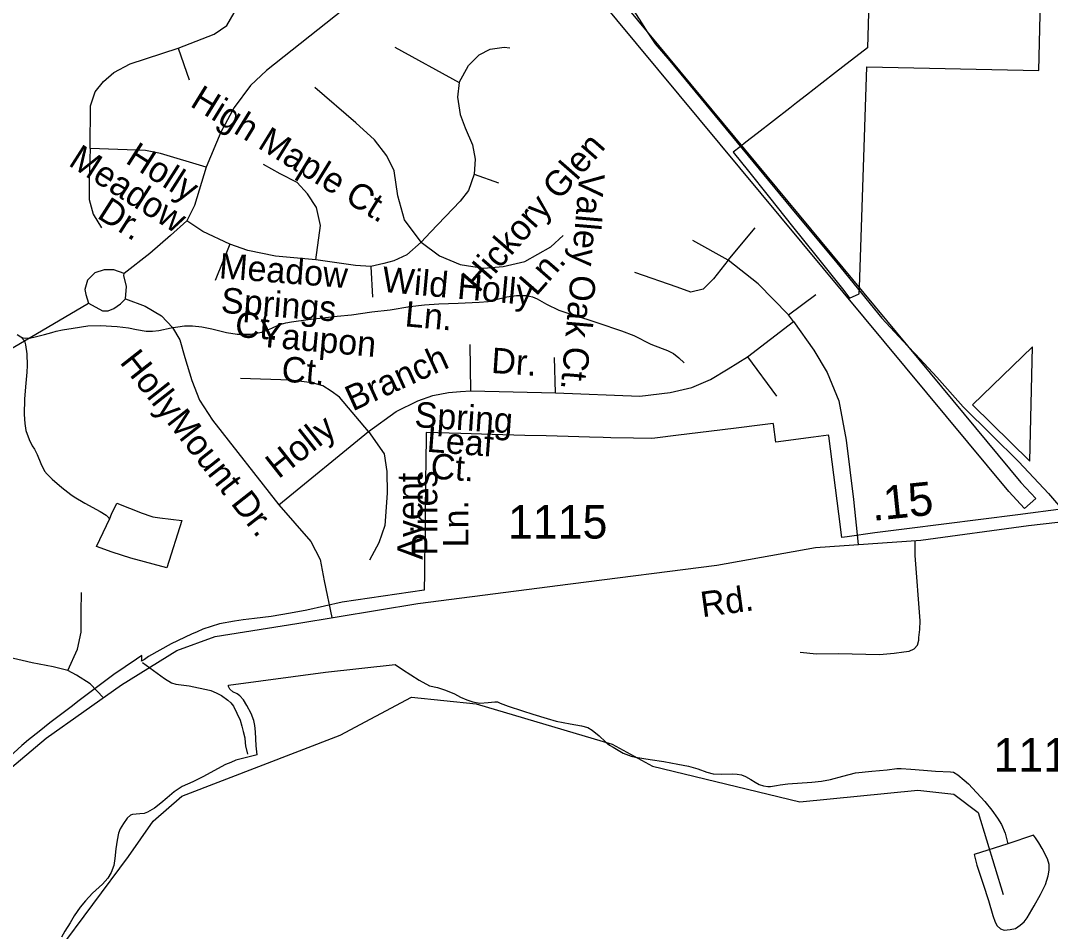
# Model space of a CAD drawing. Extents: x 2001466 to 2224147, y 644118 to 847247.
# Drawn here: x 2039763 to 2043610, y 683440 to 686843 of the extents above; entities that cross this region are included whole.
import ezdxf

# ---------------------------------------------------------------- set-up
doc = ezdxf.new("R2010")
doc.units = 0
for name, color, linetype in [('Exist Aviation Commercial or Municipal Perimeter Paved', 7, 'Continuous'), ('Exist Boundary Political City Limit New', 7, 'Continuous'), ('Exist Boundary Political City Limit New Hole', 7, 'Continuous'), ('Exist Hydrographic Creek Single Shore', 7, 'Continuous'), ('Exist Hydrographic Misc Water Feature', 7, 'Continuous'), ('Exist Road Non-System Type 51', 7, 'Continuous'), ('Exist Road Non-System Type 51 Label', 7, 'Continuous'), ('Exist Road Secondary Mileage Hundredths English Label', 7, 'Continuous'), ('Exist Road Secondary Type 51 Attributed', 7, 'Continuous'), ('Exist Road Secondary Type 51 Label', 7, 'Continuous'), ('Exist Road Secondary Type 51 Number Label', 7, 'Continuous'), ('Map Preparation Boundary City Limit Buffer Line', 7, 'Continuous')]:
    doc.layers.add(name, color=color, linetype=linetype)

msp = doc.modelspace()

# ---------------------------------------------------------------- linework, layer by layer
at = {"layer": 'Exist Aviation Commercial or Municipal Perimeter Paved'}
msp.add_line((2042103.6, 686800.8), (2043075.5, 685628.1), dxfattribs=at)
msp.add_lwpolyline([(2043075.5, 685628.1), (2043498.8, 685117.4), (2043555, 685057.6), (2043513, 685019.5), (2043454.9, 685083.5), (2041370.9, 687591.4), (2041340.9, 687627.4), (2041386.6, 687665.5), (2041415.7, 687630.7), (2042103.6, 686800.8)], dxfattribs=at)
at = {"layer": 'Exist Boundary Political City Limit New'}
for points in [[(2042930.2, 686871.1), (2042926.1, 686741.4), (2042834.8, 686670.2), (2042806.5, 686648.1), (2042756, 686608.8), (2042699, 686564.4), (2042661.1, 686535.4), (2042636.1, 686515.7), (2042575.5, 686468), (2042514.4, 686420.4), (2042471.8, 686388.4), (2042450.8, 686370.8), (2042425.1, 686350.8), (2042430, 686344.8), (2042477.1, 686286.3), (2042560.4, 686181.8), (2042646.8, 686073.6), (2042688.1, 686021.7), (2042738.1, 685959), (2042837.9, 685833.9), (2042858.9, 685805.8), (2042896, 685822.4), (2042897.2, 685846.9), (2042909.2, 686219.6), (2042923.8, 686669.9), (2043566.8, 686655.9), (2043576.2, 687073.3)], [(2043658.9, 685019.1), (2043488.1, 684995.6), (2043073, 684943.5), (2042953.8, 684929.1), (2042851, 684914), (2042831.2, 684911.6), (2042819.6, 685000), (2042781.8, 685290.9), (2042781.5, 685293.2), (2042724.6, 685285.8), (2042584, 685267.6), (2042575, 685334.9), (2042574.6, 685337.9), (2042525, 685331.6), (2042435.9, 685320.3), (2042334.5, 685307.5), (2042220.9, 685293.6), (2042132.2, 685282.6), (2042119.5, 685281.2), (2042051.9, 685283.1), (2041968.4, 685284.3), (2041939.2, 685284.8), (2041887.8, 685286.2), (2041807.9, 685288.5), (2041725.9, 685290.8), (2041646, 685293.1), (2041564.5, 685295.2), (2041484.6, 685297.6), (2041407.5, 685299.9), (2041277.6, 685303.4), (2041277.5, 685299.9), (2041276.2, 685184.2), (2041275.6, 685139.5), (2041275.4, 685103.9), (2041274.5, 685022.6), (2041274.4, 685000), (2041274.2, 684927.7), (2041272.1, 684828.3), (2041271.4, 684777.7), (2041271, 684714.9), (2040964.2, 684669.4), (2040832.1, 684640.4), (2040770.9, 684628.4), (2040699.2, 684616.1), (2040636.6, 684608.4), (2040594, 684603.8), (2040561.5, 684599.2), (2040505.6, 684588.4), (2040444, 684568.5), (2040422.9, 684559.6), (2040401.1, 684550.4), (2040325, 684514.6), (2040241.5, 684466.3), (2040225.5, 684455.8), (2040215.2, 684449.1), (2040215.5, 684452.9)], [(2040215.5, 684452.9), (2040216.4, 684470.1), (2040196.1, 684457.2), (2040153.8, 684428.8), (2040111.9, 684399.7), (2040085.9, 684380.9), (2039982.4, 684302.1), (2039952.1, 684279.2), (2039912.2, 684249), (2039872.5, 684218.6), (2039832.4, 684187.2), (2039792.6, 684155.2), (2039767.6, 684133.8), (2039692.2, 684065)]]:
    msp.add_lwpolyline(points, dxfattribs=at)
at = {"layer": 'Exist Boundary Political City Limit New Hole'}
msp.add_lwpolyline([(2043542.8, 685623.9), (2043318.8, 685407.2), (2043532.6, 685196.8), (2043542.8, 685623.9)], dxfattribs=at)
at = {"layer": 'Exist Hydrographic Creek Single Shore'}
msp.add_lwpolyline([(2039064.6, 682482.2), (2039450.9, 683035.3), (2039650, 683211.6), (2039900, 683360.8), (2040165.9, 683719.5), (2040258, 683852.2), (2040365.8, 683945.1), (2040957, 684172.6), (2041223, 684314.8), (2041464.9, 684290.2), (2041972.8, 684138.8), (2042122.9, 684057), (2042673.9, 683924.4), (2043115, 683967.9), (2043248.9, 683952.1), (2043339.9, 683884.6), (2043432.8, 683577.6)], dxfattribs=at)
at = {"layer": 'Exist Hydrographic Misc Water Feature'}
for points in [[(2039763.8, 685661.6), (2039771.8, 685657.6), (2039781.8, 685655.6), (2039801.9, 685657.6), (2039817.9, 685661.6), (2039851.8, 685669.7), (2039879.7, 685677.8), (2039895.6, 685681.8), (2039919.6, 685687.8), (2039959.8, 685694), (2040013.8, 685702), (2040061.7, 685704.1), (2040123.7, 685700.2), (2040165.7, 685694.3), (2040195.6, 685688.4), (2040231.7, 685682.4), (2040255.7, 685682.5), (2040279.7, 685684.5), (2040325.6, 685694.6), (2040375.7, 685702.7), (2040405.6, 685702.8), (2040439.7, 685698.8), (2040477.6, 685690.9), (2040531.7, 685677), (2040571.7, 685671.1), (2040595.7, 685671.1), (2040621.7, 685671.2), (2040663.6, 685679.2), (2040701.5, 685693.3), (2040727.5, 685705.4), (2040753.6, 685713.4), (2040775.5, 685717.4), (2040837.5, 685725.6), (2040945.5, 685737.8), (2040999.4, 685743.9), (2041075.5, 685754), (2041143.4, 685762.1), (2041217.4, 685774.3), (2041271.3, 685780.4), (2041325.3, 685784.5), (2041397.5, 685786.6), (2041475.4, 685790.8), (2041509.4, 685792.8), (2041533.2, 685798.9), (2041579.1, 685811), (2041615.2, 685815), (2041653.2, 685815.1), (2041675.3, 685811.1), (2041693.1, 685803.2), (2041727.2, 685783.3), (2041773.3, 685761.4), (2041829.3, 685741.5), (2041881.4, 685725.6), (2041919.3, 685713.6), (2042007.5, 685683.8), (2042053.4, 685665.9), (2042117.4, 685634), (2042159.4, 685618.1), (2042179.5, 685610.2), (2042201.7, 685598.3), (2042221.6, 685582.3), (2042241.7, 685564.3)], [(2039749.9, 685669.5), (2039763.8, 685661.6)], [(2039763.8, 685661.6), (2039777.9, 685645.6), (2039781.8, 685631.6), (2039785.9, 685597.6), (2039788, 685553.6), (2039786.2, 685529.6), (2039782.1, 685487.6), (2039778.2, 685429.6), (2039776.3, 685371.6), (2039778.6, 685337.6), (2039782.5, 685311.6), (2039794.6, 685277.7), (2039806.7, 685253.7), (2039814.7, 685241.7), (2039824.5, 685221.8), (2039838.6, 685187.7), (2039852.8, 685159.8), (2039862.6, 685147.8), (2039880.9, 685129.9), (2039916.8, 685097.9), (2039950.8, 685072), (2039962.9, 685064), (2040002.9, 685040.2), (2040060.9, 685008.2), (2040082.9, 684994.3), (2040091.1, 684986.3), (2040097, 684982.3)], [(2040097, 684982.3), (2040103, 684998.3), (2040123.1, 685040.3), (2040217, 685002.5), (2040249, 684990.6), (2040257, 684988.6), (2040283, 684984.6), (2040365, 684974.8), (2040309.2, 684798.7), (2040175.3, 684834.4), (2040105.4, 684856.3), (2040047.2, 684878.2), (2040097, 684982.3)], [(2040646.6, 684099.5), (2040642.7, 684133.5), (2040640.4, 684185.4), (2040638.3, 684209.4), (2040634.2, 684227.5), (2040624.4, 684253.4), (2040608.4, 684283.4), (2040596.1, 684305.3), (2040582.2, 684319.3), (2040572.1, 684327.3), (2040556.1, 684335.3), (2040544.2, 684345.3), (2040540.1, 684355.3), (2040540.1, 684359.3), (2040901.8, 684407.9), (2041161.8, 684436.4), (2041189.9, 684418.5), (2041251.9, 684378.6), (2041290, 684356.7)], [(2041290, 684356.7), (2041320.1, 684350.7), (2041350.1, 684340.8), (2041384.1, 684326.8), (2041406.1, 684314.9), (2041430.1, 684305), (2041452, 684297), (2041478, 684293), (2041510, 684295.1), (2041534, 684297.1), (2041544.1, 684297.1), (2041554.1, 684293.1), (2041584, 684281.2), (2041638.2, 684263.4), (2041676.1, 684251.4), (2041730.3, 684235.5), (2041764.1, 684225.6), (2041816.2, 684215.7), (2041858.2, 684207.8), (2041882.2, 684201.8), (2041898.2, 684191.9), (2041924.2, 684169.9), (2041948.2, 684148), (2041962.4, 684136), (2041976.3, 684128), (2042014.2, 684106.1), (2042044.4, 684094.2), (2042060.4, 684090.2), (2042114.5, 684082.3), (2042166.4, 684074.4), (2042218.5, 684064.5), (2042258.5, 684056.6), (2042292.5, 684046.6), (2042326.3, 684034.7), (2042350.3, 684028.7), (2042380.5, 684026.8), (2042420.5, 684028.9), (2042440.3, 684026.9), (2042456.3, 684025), (2042470.5, 684019), (2042490.4, 684007), (2042506.4, 683997.1), (2042522.4, 683989.1), (2042538.6, 683983.1), (2042554.6, 683981.2), (2042564.6, 683981.2), (2042586.3, 683985.3), (2042600.5, 683987.3), (2042628.4, 683991.3), (2042718.4, 683997.5), (2042754.5, 684001.6), (2042788.3, 684007.6), (2042834.5, 684019.7), (2042882.2, 684031.8), (2042942.3, 684037.9), (2043000.3, 684044), (2043036.2, 684048.1), (2043052.2, 684048.1), (2043088.3, 684046.2), (2043136.3, 684042.3), (2043180.4, 684038.3), (2043236.4, 684036.5), (2043248.3, 684034.5), (2043264.2, 684024.5), (2043288.2, 684004.6), (2043304.2, 683990.6), (2043364.3, 683924.7), (2043390.6, 683892.8), (2043412.5, 683862.8), (2043426.6, 683838.8), (2043440.6, 683806.9), (2043450.8, 683766.9)], [(2040646.6, 684099.5), (2040606.8, 684089.4), (2040566.6, 684079.3), (2040548.7, 684071.3), (2040528.6, 684063.3), (2040484.8, 684039.2), (2040446.8, 684019.1), (2040406.8, 683999.1), (2040366.9, 683981), (2040336.9, 683961), (2040310.9, 683938.9), (2040287.1, 683918.8), (2040263.1, 683900.8), (2040237.1, 683884.8), (2040225, 683880.7), (2040209, 683878.7), (2040181.1, 683876.6), (2040173.1, 683874.6), (2040161.2, 683862.6), (2040147.2, 683842.6), (2040135.2, 683822.6), (2040129.2, 683806.6), (2040123.3, 683780.6), (2040119.4, 683748.5), (2040115.5, 683712.5), (2040111.4, 683686.5), (2040101.5, 683660.5), (2040089.6, 683638.5), (2040069.5, 683616.4), (2040031.6, 683582.4), (2040005.8, 683554.4), (2039985.9, 683530.3), (2039963.7, 683498.3), (2039947.9, 683472.3), (2039927.8, 683440.2), (2039915.9, 683418.2)], [(2043450.8, 683766.9), (2043324.7, 683726.7), (2043335, 683686.7), (2043359, 683616.8), (2043379.1, 683554.8), (2043395.3, 683498.8), (2043403.3, 683474.9), (2043411.3, 683460.9), (2043423.4, 683448.9), (2043437.3, 683445), (2043459.2, 683447), (2043479.3, 683451), (2043497.2, 683463.1), (2043511.3, 683475.1), (2043523.2, 683491.1), (2043549.1, 683535.1), (2043573.1, 683577.2), (2043591.1, 683615.2), (2043600.9, 683647.2), (2043604.8, 683669.2), (2043604.8, 683689.2), (2043598.7, 683711.2), (2043578.8, 683749.1), (2043566.7, 683771.1), (2043554.6, 683789.1), (2043546.6, 683799.1), (2043450.8, 683766.9)]]:
    msp.add_lwpolyline(points, dxfattribs=at)
at = {"layer": 'Exist Road Non-System Type 51'}
msp.add_line((2043104.9, 684843.7), (2043104, 684899.7), dxfattribs=at)
for points in [[(2040352, 686739.3), (2040485.7, 686791.6), (2040534.1, 686824.6), (2040561.3, 686871.1), (2040576.8, 686937), (2040573.8, 687066)], [(2040968.8, 686884.5), (2040681.4, 686655.9), (2040621.3, 686599.7), (2040561.3, 686518.2), (2040510.9, 686425.2), (2040456.6, 686295.3)], [(2042053.8, 686879.3), (2042090.6, 686820.5), (2042103.6, 686800.8)], [(2042103.6, 686800.8), (2042133.3, 686755.6), (2042188, 686692.5), (2042340.2, 686507.4), (2042638.8, 686145.3), (2042812.6, 685937.8), (2042980.4, 685730.4), (2043075.5, 685628.1)], [(2041160.7, 686743.1), (2041400.9, 686611.3)], [(2041400.9, 686611.3), (2041435.8, 686675.3), (2041476.5, 686714.1), (2041517.2, 686735.4), (2041569.5, 686743.1), (2041590.8, 686741.2)], [(2040022.6, 686365.1), (2040024.6, 686524.1), (2040042, 686576.4), (2040073, 686615.2), (2040111.8, 686648.1), (2040171.8, 686681.1), (2040352, 686739.3)], [(2040352, 686739.3), (2040392.7, 686621)], [(2041259.5, 686015.3), (2041197.5, 686098.7), (2041172.3, 686187.9), (2041158.8, 686280.9), (2041131.6, 686337.2), (2041085.1, 686397.3), (2041015.4, 686461.2), (2040862.3, 686593.1)], [(2041400.9, 686611.3), (2041395.1, 686556.2), (2041404.8, 686492.3), (2041424.2, 686441.9), (2041451.3, 686377.9), (2041461, 686325.5), (2041457.1, 686269.3)], [(2040022.6, 686365.1), (2040019.2, 686245.8), (2040019.2, 686174.8), (2040034.4, 686119), (2040064.8, 686068.3)], [(2040456.6, 686295.3), (2040286.1, 686345.7), (2040229.9, 686357.3), (2040022.6, 686365.1)], [(2040456.6, 686295.3), (2040412.1, 686152.2), (2040383.8, 686094.1)], [(2040866.2, 685948.6), (2040883.6, 686076.6), (2040868.1, 686144.5), (2040835.2, 686194.9), (2040796.5, 686237.5), (2040732.5, 686270.5), (2040670.5, 686305.4)], [(2041457.1, 686269.3), (2041435.8, 686207.3), (2041404.8, 686168.5), (2041294.4, 686052.2), (2041259.5, 686015.3)], [(2041457.1, 686269.3), (2041548.2, 686236.4)], [(2040383.8, 686094.1), (2040322.9, 686039.8), (2040245.4, 685971.9), (2040150.5, 685898.2), (2040111.8, 685911.8), (2040074.9, 685911.8), (2040040.1, 685900.2), (2040013, 685873), (2040003.3, 685838.1), (2040006.5, 685819.7), (2040016.7, 685786.8), (2040069.1, 685758.6), (2040090.4, 685758.6), (2040111.8, 685766.4), (2040136.9, 685783.9), (2040154.4, 685803.2), (2040158.3, 685849.8), (2040148.6, 685890.5), (2040150.5, 685898.2)], [(2040544.6, 686006.8), (2040443.8, 686055.3), (2040383.8, 686094.1)], [(2042405.7, 685947.9), (2042506.5, 686068.1)], [(2041259.5, 686015.3), (2041205.3, 685968), (2041156.8, 685944.8), (2041120, 685935.1), (2041071.6, 685923.4)], [(2041259.5, 686015.3), (2041327.3, 685964.2), (2041404.8, 685931.2), (2041492, 685917.6), (2041565.6, 685923.4), (2041647, 685942.8), (2041743.9, 685997.1), (2041790.4, 686039.8)], [(2042405.7, 685947.9), (2042274, 686021.5)], [(2040544.6, 686006.8), (2040490.3, 685871.1)], [(2040866.2, 685948.6), (2040715.1, 685962.2), (2040612.4, 685983.5), (2040544.6, 686006.8)], [(2041071.6, 685923.4), (2041013.5, 685927.3), (2040866.2, 685948.6)], [(2042405.7, 685947.9), (2042351.5, 685878.1), (2042312.7, 685839.3), (2042266.2, 685827.7), (2042215.8, 685847.1), (2042057, 685901.3)], [(2042631.2, 685743.5), (2042518.1, 685858.7), (2042405.7, 685947.9)], [(2041071.6, 685923.4), (2041077.4, 685809.1)], [(2042631.2, 685743.5), (2042733.9, 685819.1)], [(2039494.6, 685297.3), (2039550.4, 685431.7), (2039598.5, 685507.8), (2039654.3, 685571.2), (2039735.4, 685621.9), (2040016.7, 685786.8)], [(2040154.4, 685803.2), (2040228, 685776.1), (2040290, 685739.3), (2040330.7, 685696.6), (2040357.8, 685649.7), (2040377.2, 685583.8), (2040402.4, 685498.5), (2040431.4, 685424.8), (2040479.9, 685349.2), (2040727.9, 685034)], [(2042650.6, 685718.3), (2042631.2, 685743.5)], [(2042478.2, 685586.5), (2042650.6, 685718.3)], [(2042650.6, 685718.3), (2042726.2, 685611.7), (2042776.5, 685528.3), (2042819.2, 685421.7), (2042847.4, 685274.7), (2042874.6, 685053.7), (2042891.3, 684884.8)], [(2041444.7, 685459.3), (2041442.8, 685631.9)], [(2043075.5, 685628.1), (2043105.6, 685595.8), (2043185.9, 685510.2), (2043283.6, 685400.2), (2043391.4, 685294), (2043491.4, 685193.9), (2043603, 685075.7), (2043663.5, 685004.4)], [(2041760.9, 685451.6), (2042076.7, 685439.9), (2042189.5, 685452.7), (2042270.9, 685472.1), (2042340.6, 685501.2), (2042406.5, 685541.9), (2042478.2, 685586.5)], [(2042478.2, 685586.5), (2042586.7, 685439.1)], [(2041760.9, 685451.6), (2041757, 685583.4)], [(2041063.1, 685307.3), (2040954.6, 685435.3), (2040923.6, 685458.5), (2040892.6, 685477.9), (2040851.9, 685489.6), (2040772.4, 685499.2), (2040584.5, 685505.1)], [(2041063.1, 685307.3), (2041165.7, 685381.8), (2041247.1, 685422.5), (2041303.3, 685441.9), (2041361.4, 685453.5), (2041406, 685457.4), (2041444.7, 685459.3)], [(2041444.7, 685459.3), (2041760.9, 685451.6)], [(2040727.9, 685034), (2041063.1, 685307.3)], [(2041063.1, 685307.3), (2041121.2, 685223.9), (2041130.9, 685158), (2041132.8, 685076.6), (2041123.1, 684956.4), (2041101.8, 684891.3), (2041066.9, 684827.3)], [(2040727.9, 685034), (2040847.2, 684897.1), (2040882.1, 684828.8), (2040897.6, 684749.7), (2040926.2, 684612.2)], [(2042674.9, 684482.6), (2042736.1, 684476.7), (2042818.6, 684477.7), (2042971.4, 684474.7), (2043026.4, 684479.8), (2043062.1, 684483.8), (2043082.5, 684486.9), (2043100.8, 684495), (2043113, 684509.3), (2043118.1, 684527.7), (2043118.1, 684537.9), (2043122.2, 684567.4), (2043123.2, 684600.1), (2043104.9, 684843.7)], [(2039939.5, 684414.5), (2039975.7, 684494.5), (2039989, 684557.4), (2039989, 684633.6), (2039990.9, 684706)], [(2039939.5, 684414.5), (2039884.3, 684427.8), (2039806.2, 684443.1), (2039714.9, 684464), (2039646.3, 684502.1), (2039589.2, 684549.8), (2039551.1, 684597.4)], [(2040218.1, 684444.6), (2040300.8, 684384.9), (2040326.5, 684368.4), (2040342.4, 684364.1), (2040392.3, 684357.1), (2040428.1, 684350.3), (2040458, 684343.7), (2040473.9, 684339.4), (2040493.7, 684331), (2040513.5, 684320.6), (2040537.2, 684304.1), (2040549, 684293.9), (2040558.7, 684281.7), (2040583.7, 684229.2), (2040589.2, 684207), (2040594.8, 684186.9), (2040600.3, 684162.8), (2040601.9, 684144.8), (2040603.7, 684132.7), (2040611.1, 684102.6)], [(2040072.3, 684312.5), (2040023.3, 684365), (2039971.9, 684397.4), (2039939.5, 684414.5)]]:
    msp.add_lwpolyline(points, dxfattribs=at)
at = {"layer": 'Exist Road Secondary Type 51 Attributed'}
msp.add_lwpolyline([(2037187.4, 681968.8), (2037383.7, 682053.3), (2037727.8, 682241.3), (2038421.4, 682680.8), (2038558.6, 682797), (2038816.2, 683031.5), (2039015.7, 683215.3), (2039218.4, 683462.5), (2039461.2, 683764.6), (2039707.1, 684032.9), (2039859.1, 684161.8), (2040139.9, 684360.4), (2040346.8, 684489.2), (2040490.4, 684542), (2040794.4, 684590.6), (2041247.3, 684664.6), (2041817.3, 684738.5), (2042364.1, 684808.2), (2042732.5, 684873.7), (2043125.2, 684901.2), (2043528.4, 684956.1), (2043735.4, 684980.4)], dxfattribs=at)
at = {"layer": 'Map Preparation Boundary City Limit Buffer Line'}
for points in [[(2042930.2, 686871.1), (2042926.1, 686741.4), (2042834.8, 686670.2), (2042806.5, 686648.1), (2042756, 686608.8), (2042699, 686564.4), (2042661.1, 686535.4), (2042636.1, 686515.7), (2042575.5, 686468), (2042514.4, 686420.4), (2042471.8, 686388.4), (2042450.8, 686370.8), (2042425.1, 686350.8), (2042430, 686344.8), (2042477.1, 686286.3), (2042560.4, 686181.8), (2042646.8, 686073.6), (2042688.1, 686021.7), (2042738.1, 685959), (2042837.9, 685833.9), (2042858.9, 685805.8), (2042896, 685822.4), (2042897.2, 685846.9), (2042909.2, 686219.6), (2042923.8, 686669.9), (2043566.8, 686655.9), (2043576.2, 687073.3)], [(2043542.8, 685623.9), (2043318.8, 685407.2), (2043532.6, 685196.8), (2043542.8, 685623.9)], [(2043658.9, 685019.1), (2043488.1, 684995.6), (2043073, 684943.5), (2042953.8, 684929.1), (2042851, 684914), (2042831.2, 684911.6), (2042819.6, 685000), (2042781.8, 685290.9), (2042781.5, 685293.2), (2042724.6, 685285.8), (2042584, 685267.6), (2042575, 685334.9), (2042574.6, 685337.9), (2042525, 685331.6), (2042435.9, 685320.3), (2042334.5, 685307.5), (2042220.9, 685293.6), (2042132.2, 685282.6), (2042119.5, 685281.2), (2042051.9, 685283.1), (2041968.4, 685284.3), (2041939.2, 685284.8), (2041887.8, 685286.2), (2041807.9, 685288.5), (2041725.9, 685290.8), (2041646, 685293.1), (2041564.5, 685295.2), (2041484.6, 685297.6), (2041407.5, 685299.9), (2041277.6, 685303.4), (2041277.5, 685299.9), (2041276.2, 685184.2), (2041275.6, 685139.5), (2041275.4, 685103.9), (2041274.5, 685022.6), (2041274.4, 685000), (2041274.2, 684927.7), (2041272.1, 684828.3), (2041271.4, 684777.7), (2041271, 684714.9), (2040964.2, 684669.4), (2040832.1, 684640.4), (2040770.9, 684628.4), (2040699.2, 684616.1), (2040636.6, 684608.4), (2040594, 684603.8), (2040561.5, 684599.2), (2040505.6, 684588.4), (2040444, 684568.5), (2040422.9, 684559.6), (2040401.1, 684550.4), (2040325, 684514.6), (2040241.5, 684466.3), (2040225.5, 684455.8), (2040215.2, 684449.1), (2040215.5, 684452.9)], [(2040215.5, 684452.9), (2040216.4, 684470.1), (2040196.1, 684457.2), (2040153.8, 684428.8), (2040111.9, 684399.7), (2040085.9, 684380.9), (2039982.4, 684302.1), (2039952.1, 684279.2), (2039912.2, 684249), (2039872.5, 684218.6), (2039832.4, 684187.2), (2039792.6, 684155.2), (2039767.6, 684133.8), (2039692.2, 684065)]]:
    msp.add_lwpolyline(points, dxfattribs=at)

# ---------------------------------------------------------------- texts
at = {"layer": 'Exist Road Non-System Type 51 Label'}
for s, rotation, p in [('High Maple Ct.', 328.3602, (2040392.3, 686525)), ('Hickory Glen', 48.8497, (2041473.5, 685822.4)), ('Meadow', 327.4959, (2039937.7, 686303.9)), ('Holly', 327.4959, (2040150.8, 686313.1)), ('Valley Oak Ct.', 265.0603, (2041850.9, 686274.9)), ('Dr.', 327.4959, (2040044.6, 686107.9)), ('Meadow', 355.5957, (2040502.5, 685880.1)), ('Ln.', 48.8497, (2041688.9, 685809.9)), ('Wild Holly', 354.799, (2041110.4, 685829.7)), ('Springs', 355.5957, (2040509.2, 685751.4)), ('Ln.', 354.799, (2041195.9, 685700.7)), ('Ct.', 355.5957, (2040562, 685661.1)), ('Yaupon', 354.799, (2040650.6, 685625.1)), ('HollyMount Dr.', 308.1985, (2040130.7, 685565.9)), ('Ct.', 354.799, (2040734.8, 685495.1)), ('Branch', 24.4715, (2041003.5, 685381.9)), ('Dr.', 356.1811, (2041519.1, 685526.5)), ('Spring', 356.1811, (2041232.6, 685324.3)), ('Holly', 38.2691, (2040726.4, 685128.1)), ('Leaf', 355.5957, (2041278.3, 685232)), ('Ct.', 356.1811, (2041292.3, 685131.7)), ('Avent', 90, (2041264.8, 684828.3)), ('Pines', 90, (2041319.5, 684843.8)), ('Ln.', 90, (2041436, 684874.4))]:
    msp.add_text(s, height=95, rotation=rotation, dxfattribs=at).set_placement(p)
at = {"layer": 'Exist Road Secondary Mileage Hundredths English Label'}
msp.add_text('.15', height=125, rotation=5.8847, dxfattribs=at).set_placement((2042945.9, 684973.4))
at = {"layer": 'Exist Road Secondary Type 51 Label'}
msp.add_text('Rd.', height=95, rotation=7.7237, dxfattribs=at).set_placement((2042309.5, 684613.3))
at = {"layer": 'Exist Road Secondary Type 51 Number Label'}
for s, p in [('1115', (2041583.3, 684907.6)), ('1116', (2043397, 684036.9))]:
    msp.add_text(s, height=125, dxfattribs=at).set_placement(p)

doc.saveas('drawing.dxf')
